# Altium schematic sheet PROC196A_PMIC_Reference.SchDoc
size 431 x 279 mm; Date: Not shown in title block; ApprovedBy: Not shown in title block; CheckedBy: Not shown in title block; Author: Not shown in title block; CompanyName: Not shown in title block; Engineer: Not shown in title block; Organization: Not shown in title block; Address1: Not shown in title block; Address2: Not shown in title block; Address3: Not shown in title block; Address4: Not shown in title block; DocumentNumber: 6; Revision: Use project parameter SCH_Rev; SheetNumber: 6; SheetTotal: 25; PageSetup: Record=PageOptions¦CenterHorizontal=True¦CenterVertical=True¦PrintScale=1.00¦XCorrection=1.00¦YCorrection=1.00¦PrintKind=0¦BorderSize=5000000¦LeftOffset=0¦BottomOffset=0¦Orientation=2¦PaperLength=1000¦PaperWidth=1000¦Scale=100¦PaperSource=15¦PrintQuality=600¦MediaType=1¦DitherType=10¦PaperKind=Letter¦PrintScaleMode=1
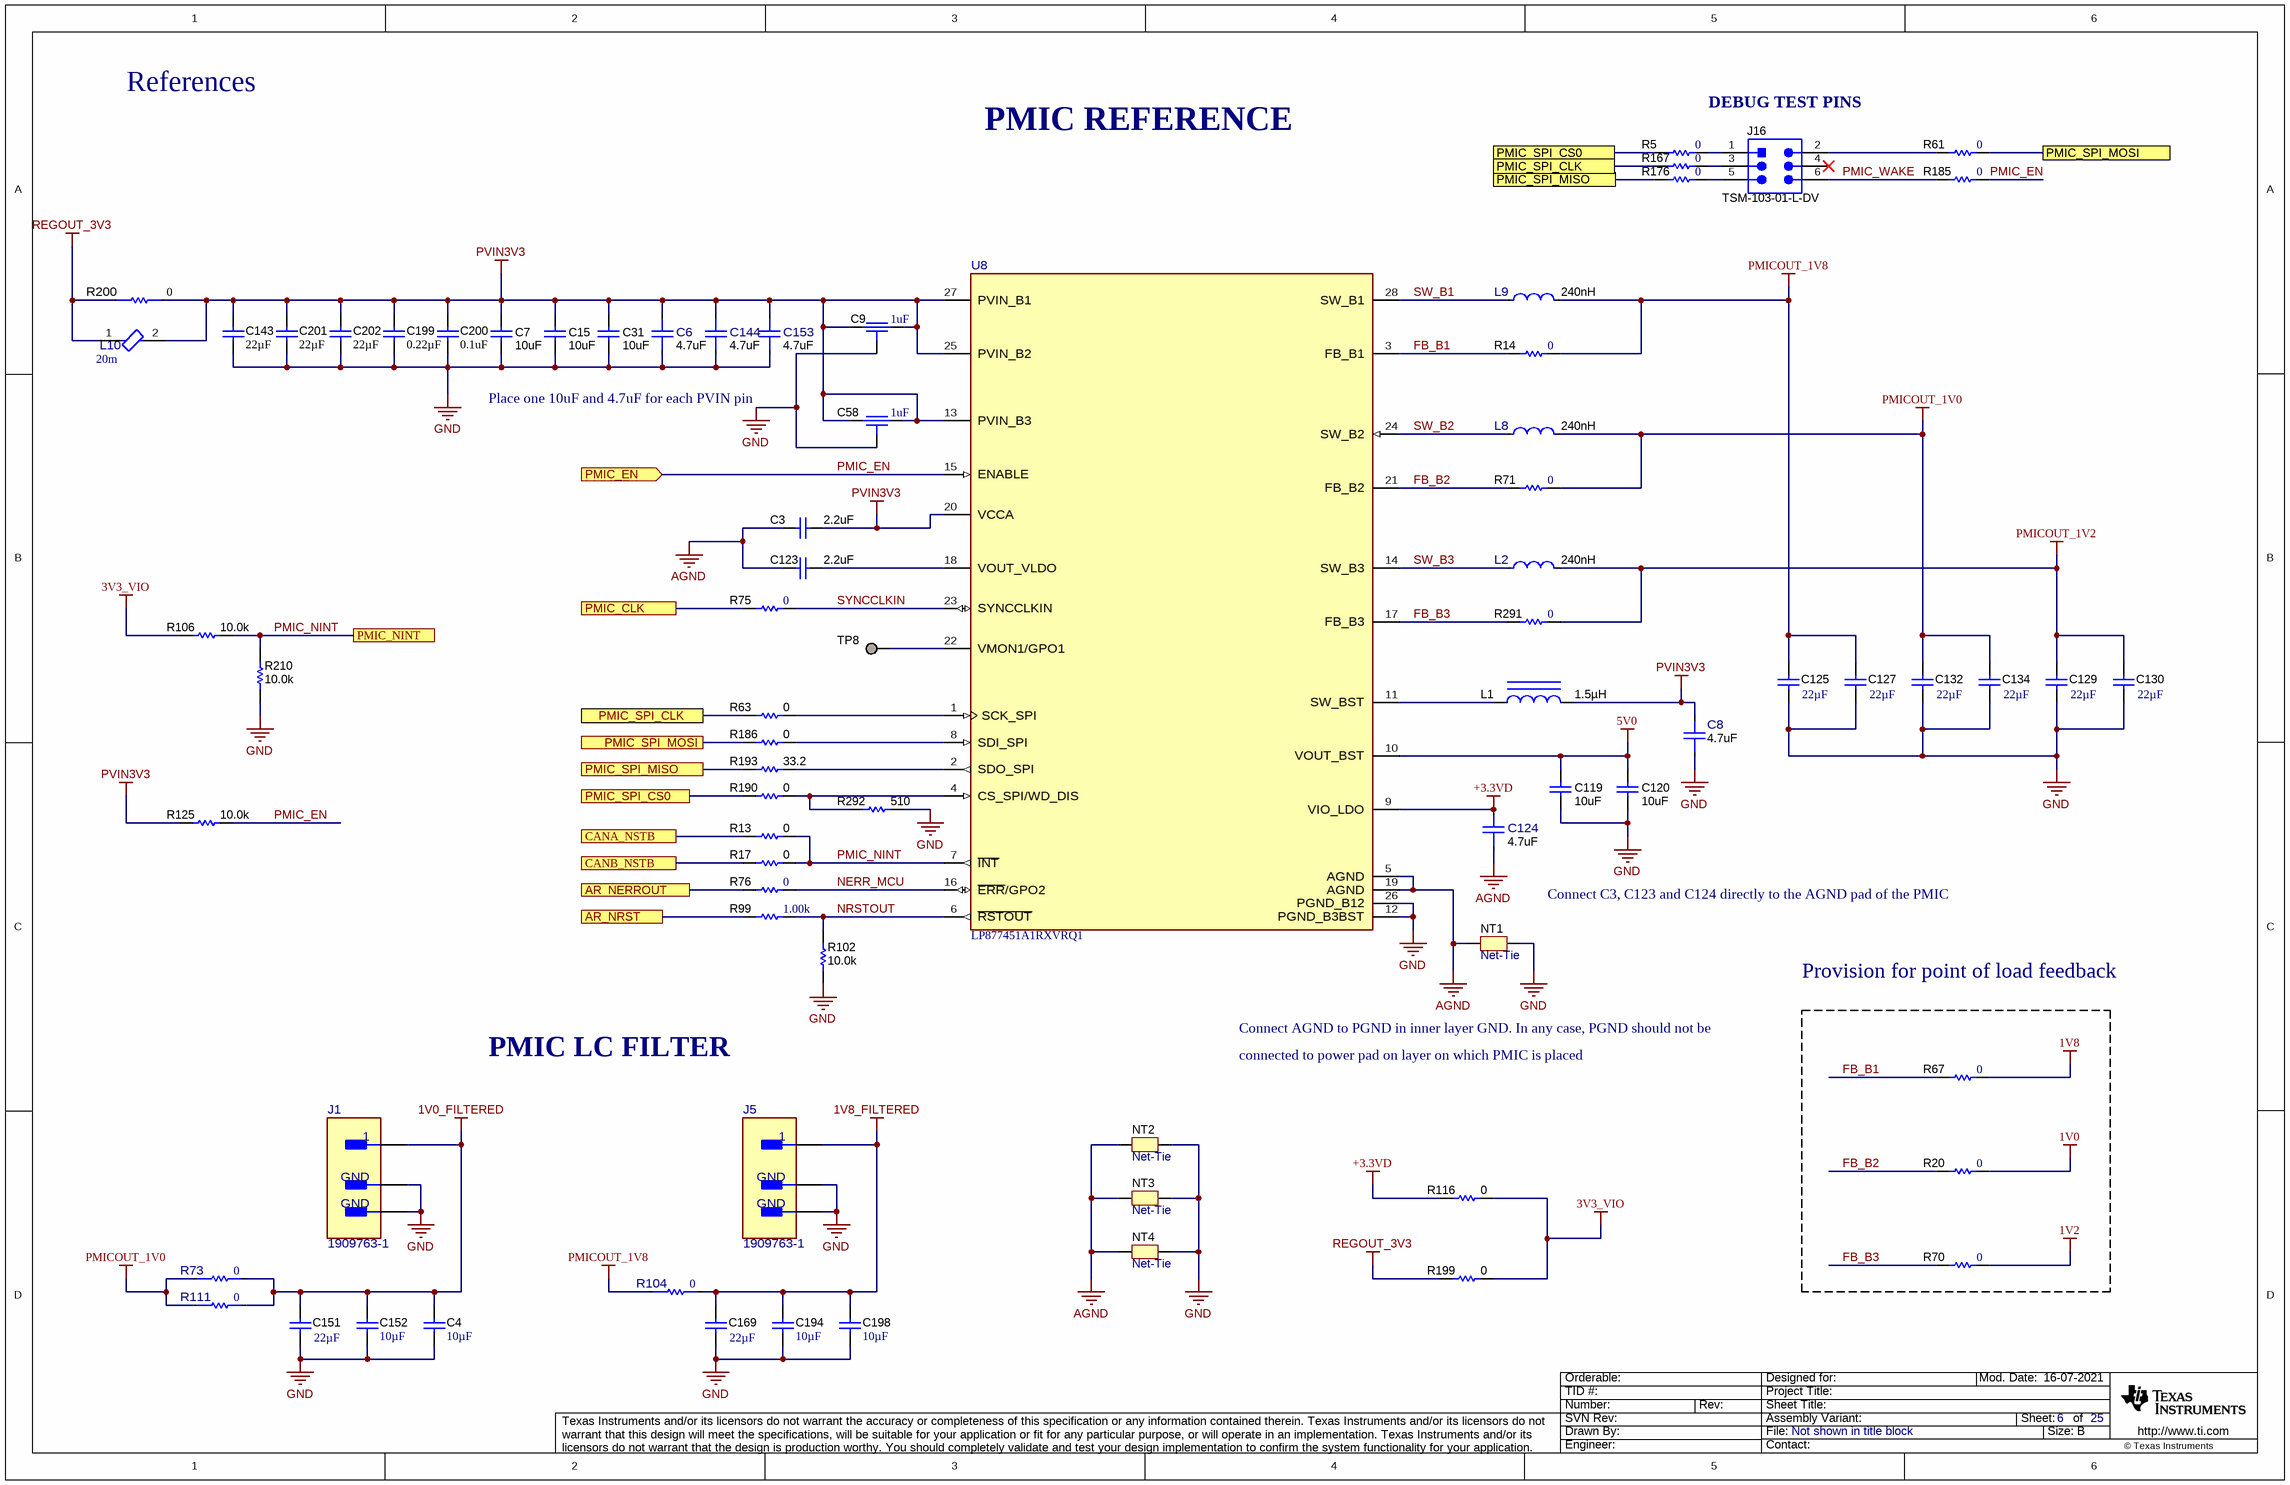
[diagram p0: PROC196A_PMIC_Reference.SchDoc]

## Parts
C3  ValueDisplayed: 2.2uF  [0603L]  (hidden comment: GCM188R70J225KE22D)
C4  Cap_F: 10µF  [0805L]  (hidden comment: C0805C106J8RACAUTO)
C6  ValueDisplayed: 4.7uF  [FP-GCJ188C70J475KE02J_0603-MFG]  (hidden comment: GCJ188C70J475KE02J)
C7  ValueDisplayed: 10uF  [0805L]  (hidden comment: GCM21BR71A106KE22L)
C8  ValueDisplayed: 4.7uF  [FP-GCJ188C70J475KE02J_0603-MFG]  (hidden comment: GCJ188C70J475KE02J)
C9  ValueDisplayed: 1uF  [FP-NFM18HC105C1C3D_0603-MFG]  (hidden comment: NFM18HC105C1C3D)
C15  ValueDisplayed: 10uF  [0805L]  (hidden comment: GCM21BR71A106KE22L)
C31  ValueDisplayed: 10uF  [0805L]  (hidden comment: GCM21BR71A106KE22L)
C58  ValueDisplayed: 1uF  [FP-NFM18HC105C1C3D_0603-MFG]  (hidden comment: NFM18HC105C1C3D)
C119  ValueDisplayed: 10uF  [0805L]  (hidden comment: GCM21BR71A106KE22L)
C120  ValueDisplayed: 10uF  [0805L]  (hidden comment: GCM21BR71A106KE22L)
C123  ValueDisplayed: 2.2uF  [0603L]  (hidden comment: GCM188R70J225KE22D)
C124  ValueDisplayed: 4.7uF  [FP-GCJ188C70J475KE02J_0603-MFG]  (hidden comment: GCJ188C70J475KE02J)
C125  ValueDisplayed: 22µF  [0805_155]  (hidden comment: CGA4J1X7T0J226M)
C127  ValueDisplayed: 22µF  [0805_155]  (hidden comment: CGA4J1X7T0J226M)
C129  ValueDisplayed: 22µF  [0805_155]  (hidden comment: CGA4J1X7T0J226M)
C130  ValueDisplayed: 22µF  [0805_155]  (hidden comment: CGA4J1X7T0J226M)
C132  ValueDisplayed: 22µF  [0805_155]  (hidden comment: CGA4J1X7T0J226M)
C134  ValueDisplayed: 22µF  [0805_155]  (hidden comment: CGA4J1X7T0J226M)
C143  ValueDisplayed: 22µF  [0805_155]  (hidden comment: CGA4J1X7T0J226M)
C144  ValueDisplayed: 4.7uF  [FP-GCJ188C70J475KE02J_0603-MFG]  (hidden comment: GCJ188C70J475KE02J)
C151  ValueDisplayed: 22µF  [0805_155]  (hidden comment: CGA4J1X7T0J226M)
C152  Cap_F: 10µF  [0805L]  (hidden comment: C0805C106J8RACAUTO)
C153  ValueDisplayed: 4.7uF  [FP-GCJ188C70J475KE02J_0603-MFG]  (hidden comment: GCJ188C70J475KE02J)
C169  ValueDisplayed: 22µF  [0805_155]  (hidden comment: CGA4J1X7T0J226M)
C194  Cap_F: 10µF  [0805L]  (hidden comment: C0805C106J8RACAUTO)
C198  Cap_F: 10µF  [0805L]  (hidden comment: C0805C106J8RACAUTO)
C199  ValueDisplayed: 0.22µF  [0402L]  (hidden comment: GCM155R71C224KE02D)
C200  ValueDisplayed: 0.1uF  [0402L]  (hidden comment: GCM155R71C104KA55D)
C201  ValueDisplayed: 22µF  [0805_155]  (hidden comment: CGA4J1X7T0J226M)
C202  ValueDisplayed: 22µF  [0805_155]  (hidden comment: CGA4J1X7T0J226M)
J1  1909763-1  [FP-1909763-1_SMT_JACK _CONN-MFG]
J5  1909763-1  [FP-1909763-1_SMT_JACK _CONN-MFG]
J16  TSM-103-01-L-DV  [Samtec_TSM-103-01-x-DV]
L1  ValueDisplayed: 1.5µH  [TFM201610ALMA]  (hidden comment: TFM201610ALMA1R5MTAA)
L2  Ind_H: 240nH  [FP-TFM201610ALMAR24MTAA_0806 (2016 Metric)-MFG]  (hidden comment: TFM201610ALMAR24MTAA)
L8  Ind_H: 240nH  [FP-TFM201610ALMAR24MTAA_0806 (2016 Metric)-MFG]  (hidden comment: TFM201610ALMAR24MTAA)
L9  Ind_H: 240nH  [FP-TFM201610ALMAR24MTAA_0806 (2016 Metric)-MFG]  (hidden comment: TFM201610ALMAR24MTAA)
L10  DCR_ohm: 20m  [FP-MPZ2012S101ATD25_0805-MFG]  (hidden comment: MPZ2012S101ATD25)
NT1  Net-Tie  [Net-Tie_50milWide_30milLong]  (net tie, no BOM)
NT2  Net-Tie  [Net-Tie_50milWide_30milLong]  (net tie, no BOM)
NT3  Net-Tie  [Net-Tie_50milWide_30milLong]  (net tie, no BOM)
NT4  Net-Tie  [Net-Tie_50milWide_30milLong]  (net tie, no BOM)
R5  ValueDisplayed: 0  [0402L]  (hidden comment: ERJ-2GE0R00X)
R13  ValueDisplayed: 0  [0402L]  (hidden comment: ERJ-2GE0R00X)
R14  ValueDisplayed: 0  [0402L]  (hidden comment: ERJ-2GE0R00X)
R17  ValueDisplayed: 0  [0402L]  (hidden comment: ERJ-2GE0R00X)
R20  ValueDisplayed: 0  [0402L]  (hidden comment: ERJ-2GE0R00X)
R61  ValueDisplayed: 0  [0402L]  (hidden comment: ERJ-2GE0R00X)
R63  ValueDisplayed: 0  [0402L]  (hidden comment: ERJ-2GE0R00X)
R67  ValueDisplayed: 0  [0402L]  (hidden comment: ERJ-2GE0R00X)
R70  ValueDisplayed: 0  [0402L]  (hidden comment: ERJ-2GE0R00X)
R71  ValueDisplayed: 0  [0402L]  (hidden comment: ERJ-2GE0R00X)
R73  value 0  [FP-HCJ0603ZT0R00_0603-MFG]  (hidden comment: HCJ0603ZT0R00)
R75  ValueDisplayed: 0  [0402L]  (hidden comment: ERJ-2GE0R00X)
R76  ValueDisplayed: 0  [0402L]  (hidden comment: ERJ-2GE0R00X)
R99  ValueDisplayed: 1.00k  [0402L]  (hidden comment: CRCW04021K00FKED)
R102  ValueDisplayed: 10.0k  [0402L]  (hidden comment: CRCW040210K0FKED)
R104  value 0  [FP-HCJ0603ZT0R00_0603-MFG]  (hidden comment: HCJ0603ZT0R00)
R106  ValueDisplayed: 10.0k  [0402L]  (hidden comment: CRCW040210K0FKED)
R111  value 0  [FP-HCJ0603ZT0R00_0603-MFG]  (hidden comment: HCJ0603ZT0R00)
R116  ValueDisplayed: 0  [0402L]  (hidden comment: CRCW04020000Z0EDHP)
R125  ValueDisplayed: 10.0k  [0402L]  (hidden comment: CRCW040210K0FKED)
R167  ValueDisplayed: 0  [0402L]  (hidden comment: ERJ-2GE0R00X)
R176  ValueDisplayed: 0  [0402L]  (hidden comment: ERJ-2GE0R00X)
R185  ValueDisplayed: 0  [0402L]  (hidden comment: ERJ-2GE0R00X)
R186  ValueDisplayed: 0  [0402L]  (hidden comment: ERJ-2GE0R00X)
R190  ValueDisplayed: 0  [0402L]  (hidden comment: ERJ-2GE0R00X)
R193  ValueDisplayed: 33.2  [0402L]  (hidden comment: CRCW040233R2FKED)
R199  ValueDisplayed: 0  [0402L]  (hidden comment: CRCW04020000Z0EDHP)
R200  Res_ohm: 0  [FP-HCJ0603ZT0R00_0603-MFG]  (hidden comment: HCJ0603ZT0R00)
R210  ValueDisplayed: 10.0k  [0402L]  (hidden comment: CRCW040210K0FKED)
R291  ValueDisplayed: 0  [0402L]  (hidden comment: ERJ-2GE0R00X)
R292  ValueDisplayed: 510  [0402L]  (hidden comment: ERJ-2GEJ511X)
TP8  TESTPOINT  [TP_25MIL-SMT]  (value not drawn)  (no BOM)
U8  LP877451A1RXVRQ1  [RXV0028A-MFG]

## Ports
AR_NERROUT, AR_NRST, CANA_NSTB, CANB_NSTB, PMIC_CLK, PMIC_EN (in), PMIC_NINT, PMIC_SPI_CLK, PMIC_SPI_CS0, PMIC_SPI_MISO, PMIC_SPI_MOSI

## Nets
1V0: R20.2
1V0_FILTERED: C4.1 C151.1 C152.1 J1.1 R73.2 R111.2
1V2: R70.2
1V8: R67.2
1V8_FILTERED: C169.1 C194.1 C198.1 J5.1 R104.2
3V3_VIO: R106.2 R116.2 R199.2
5V0: C119.1 C120.1 U8.10(VOUT_BST)
+3.3VD: C124.2 R116.1 U8.9(VIO_LDO)
AGND: C3.1 C123.1 C124.1 NT1.2 NT2.1 NT3.1 NT4.1 U8.5(AGND) U8.19(AGND)
GND: C4.2 C6.1 C7.2 C8.1 C9.2 C15.2 C31.2 C58.2 C119.2 C120.2 C125.2 C127.2 C129.2 C130.2 C132.2 C134.2 C143.2 C144.1 C151.2 C152.2 C153.1 C169.2 C194.2 C198.2 C199.2 C200.2 C201.2 C202.2 J1.2(GND) J1.3(GND) J5.2(GND) J5.3(GND) NT1.1 NT2.2 NT3.2 NT4.2 R102.2 R210.2 R292.1 U8.12(PGND_B3BST) U8.26(PGND_B12)
PMICOUT_1V0: C132.1 C134.1 L8.2 R71.2 R73.1 R111.1
PMICOUT_1V2: C129.1 C130.1 L2.2 R291.2
PMICOUT_1V8: C125.1 C127.1 L9.2 R14.2 R104.1
PVIN3V3: C3.2 C6.2 C7.1 C8.2 C9.1 C9.3 C15.1 C31.1 C58.1 C58.3 C143.1 C144.2 C153.2 C199.1 C200.1 C201.1 C202.1 L1.2 L10.2 R125.2 R200.2 U8.13(PVIN_B3) U8.20(VCCA) U8.25(PVIN_B2) U8.27(PVIN_B1)
REGOUT_3V3: L10.1 R199.1 R200.1
AR_NERROUT: R76.1 ; port AR_NERROUT
AR_NRST: R99.1 ; port AR_NRST
CANA_NSTB: R13.1 ; port CANA_NSTB
CANB_NSTB: R17.1 ; port CANB_NSTB
FB_B1: R14.1 R67.1 U8.3(FB_B1)
FB_B2: R20.1 R71.1 U8.21(FB_B2)
FB_B3: R70.1 R291.1 U8.17(FB_B3)
NERR_MCU: R76.2 U8.16(~{ERR}/GPO2)
NRSTOUT: R99.2 R102.1 U8.6(~{RSTOUT})
PMIC_CLK: R75.1 ; port PMIC_CLK
PMIC_EN: R125.1 R185.2 U8.15(ENABLE) ; port PMIC_EN
PMIC_NINT: R13.2 R17.2 R106.1 R210.1 U8.7(~{INT}) ; port PMIC_NINT
PMIC_SPI_CLK: R63.2 R167.1 ; port PMIC_SPI_CLK
PMIC_SPI_CS0: R5.1 R190.1 ; port PMIC_SPI_CS0
PMIC_SPI_MISO: R176.1 R193.2 ; port PMIC_SPI_MISO
PMIC_SPI_MOSI: R61.2 R186.2 ; port PMIC_SPI_MOSI
PMIC_WAKE: J16.6 R185.1
SW_B1: L9.1 U8.28(SW_B1)
SW_B2: L8.1 U8.24(SW_B2)
SW_B3: L2.1 U8.14(SW_B3)
SYNCCLKIN: R75.2 U8.23(SYNCCLKIN)
NetC123_2: C123.2 U8.18(VOUT_VLDO)
NetJ16_1: J16.1 R5.2
NetJ16_2: J16.2 R61.1
NetJ16_3: J16.3 R167.2
NetJ16_5: J16.5 R176.2
NetL1_1: L1.1 U8.11(SW_BST)
NetR63_1: R63.1 U8.1(SCK_SPI)
NetR186_1: R186.1 U8.8(SDI_SPI)
NetR190_2: R190.2 R292.2 U8.4(CS_SPI/WD_DIS)
NetR193_1: R193.1 U8.2(SDO_SPI)
NetTP8_1: TP8.1 U8.22(VMON1/GPO1)

Not connected (* = marked no-connect by the designer): J16 4*

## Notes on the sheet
- References
- PMIC REFERENCE
- DEBUG TEST PINS
- Place one 10uF and 4.7uF for each PVIN pin
- Connect C3, C123 and C124 directly to the AGND pad of the PMIC
- Connect AGND to PGND in inner layer GND. In any case, PGND should not be
- Provision for point of load feedback
- PMIC LC FILTER
- connected to power pad on layer on which PMIC is placed

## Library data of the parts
C3 C123 = CMP-0007134-5: CAP, CERM, 2.2 uF, 6.3 V, +/- 10%, X7R, AEC-Q200 Grade 1, 0603; Manufacturer: MuRata; TaMin_C: -55°C; Polarized: N; SizeAreaWB_mm2: 4.68; Value1: Unknown; U/M: EA; Value: 2.2uF; TaMax_C: 125°C; SizeZ_mm: 1; SizeX_mm: 1.6; SizeY_mm: 0.8; Cap_Case: 0603; Value2: 6.3V; SizeArea_mm2: 1.28; AEC Qualified: Y; Cap_F: 2.2µF; AEC Category: Q200
C4 C152 C194 C198 = CMP-0081061-1: CAP, CERM, 10 µF, 10 V,+/- 5%, X7R, AEC-Q200 Grade 1, 0805; Manufacturer: Kemet; TaMin_C: -55°C; Polarized: N; SizeAreaWB_mm2: 6.75; U/M: EA; Value: 10uF; TaMax_C: 125°C; SizeZ_mm: 1.45; SizeX_mm: 2; SizeY_mm: 1.25; Cap_Case: 0805; Value2: 10V; SizeArea_mm2: 2.5; AEC Qualified: Y; AEC Grade: 1; AEC Category: Q200
C6 C8 C124 C144 C153 = CMP-0091520-1: Cap Ceramic Multilayer 4.7uF 6.3V DC 10% SMD Paper T/R; Manufacturer: Murata; AEC Grade: Grade 1; TempCo: 22%; SizeZ_mm: 1mm; Temperature Characteristic: X7S; Cap_F: 4.7µF; Value: 4.7µF; AEC Qualified: Yes
C7 C15 C31 C119 C120 = CMP-0008017-2: CAP, CERM, 10 uF, 10 V, +/- 10%, X7R, 0805; Manufacturer: MuRata; TaMin_C: -55°C; Polarized: N; SizeAreaWB_mm2: 6.75; Value1: Unknown; U/M: EA; Value: 10uF; TaMax_C: 125°C; SizeZ_mm: 1.45; SizeX_mm: 2; SizeY_mm: 1.25; Cap_Case: 0805; Value2: 10V; SizeArea_mm2: 2.5; Cap_F: 10µF; AEC Category: Q200
C9 C58 = CMP-0088247-2: 3 Terminals Low ESL Chip Multilayer Ceramic Capacitors for Automotive; Manufacturer: Murata; VDC_V: 16V; SizeZ_mm: 0.7mm; Tolerance_%: 20%; AEC Grade: Grade 1; Cap_F: 1µF; AEC Qualified: Yes
C125 C127 C129 C130 C132 C134 = CMP-0860846-1: CAP, CERM, 22 µF, 6.3 V,+/- 20%, X7T, AEC-Q200 Grade 1, 0805; Manufacturer: TDK; Alternate PartNumber: CGA4J1X7T0J226M125AC; TaMin_C: -55°C; Polarized: N; SizeAreaWB_mm2: 6.75; U/M: EA; Value: 22uF; TaMax_C: 125°C; SizeZ_mm: 1.55; SizeX_mm: 2; SizeY_mm: 1.25; Cap_Case: 0805; Value2: 6.3V; SizeArea_mm2: 2.5; AEC Qualified: Y; AEC Grade: 1; AEC Category: Q200
C143 C201 C202 = CMP-0860846-1: CAP, CERM, 22 µF, 6.3 V,+/- 20%, X7T, AEC-Q200 Grade 1, 0805; Manufacturer: TDK; AEC Grade: 1; Value2: 6.3V; U/M: EA; Value: 22uF; TaMin_C: -55°C; TaMax_C: 125°C; SizeArea_mm2: 2.5; SizeAreaWB_mm2: 6.75; SizeX_mm: 2; Polarized: N; Cap_Case: 0805; AEC Qualified: Y; AEC Category: Q200; SizeZ_mm: 1.55; SizeY_mm: 1.25
C151 C169 = CMP-0860846-1: CAP, CERM, 22 µF, 6.3 V,+/- 20%, X7T, AEC-Q200 Grade 1, 0805; Manufacturer: TDK; TaMin_C: -55°C; Polarized: N; SizeAreaWB_mm2: 6.75; U/M: EA; Value: 22uF; TaMax_C: 125°C; SizeZ_mm: 1.55; SizeX_mm: 2; SizeY_mm: 1.25; Cap_Case: 0805; Value2: 6.3V; SizeArea_mm2: 2.5; AEC Qualified: Y; AEC Grade: 1; AEC Category: Q200
C199 = CMP-0078265-1: CAP, CERM, 0.22 µF, 16 V,+/- 10%, X7R, AEC-Q200 Grade 1, 0402; Manufacturer: MuRata; TaMin_C: -55°C; Polarized: N; SizeAreaWB_mm2: 3; U/M: EA; Value: 0.22uF; TaMax_C: 125°C; SizeZ_mm: 0.6; SizeX_mm: 1; SizeY_mm: 0.5; Cap_Case: 0402; Value2: 16V; AEC Qualified: Y; Cap_F: 220nF; AEC Category: Q200
C200 = CMP-0006351-2: CAP, CERM, 0.1 uF, 16 V, +/- 10%, X7R, 0402; Manufacturer: MuRata; TaMin_C: -55°C; Polarized: N; SizeAreaWB_mm2: 3; Value1: Unknown; U/M: EA; Value: 0.1uF; TaMax_C: 125°C; SizeZ_mm: 0.6; SizeX_mm: 1; SizeY_mm: 0.5; Cap_Case: 0402; Value2: 16V; Cap_F: 100nF; AEC Category: Q200
J1 J5 = CMP-0091846-1: U.FL (UMCC) Connector Jack, Male Pin 50Ohm Surface Mount Solder; Manufacturer: TE Connectivity; Conn Orientation: Vertical; AEC Qualified: No; SizeZ_mm: 1.5mm; Impedance: 50Ω; Frequency_Fixed: 0-6GHz; ContactFinish: Gold,Nickel; Dielectric Material: Liquid Crystal Polymer
J16 = CMP-0075648-2: Header, 2.54mm, 3x2, Gold, SMT; Manufacturer: Samtec; Pitch_mm: 2.54; Gender: Male; Cert_CSA: Y; Green_REACh: Passed; Current_A: 4.9A; Voltage_V: 475V; Shrouded: N; Green_Lifecycle: Active; Row_Count: 2
L1 = CMP-0081093-1: Inductor, Shielded, Metal Composite, 1.5 µH, 2.3 A, 0.11 ohm, AEC-Q200 Grade 0, SMD; Manufacturer: TDK; Isat: 2.8A @ 30% inductance drop; Irms: 2.3A @ 40C rise; SizeAreaWB_mm2: 7.8; DCR_ohm: 0.11; Value: 1.5uH; Imax_A: 2.3A; SizeZ_mm: 1; SizeX_mm: 2; SizeY_mm: 1.6; SizeArea_mm2: 3.2; AEC Qualified: Y; AEC Grade: 0; AEC Category: Q200
L2 L8 L9 = CMP-0091696-1: 240nH Shielded Thin Film Inductor 5A 23mOhm Max 0806 (2016 Metric); Manufacturer: TDK; SizeZ_mm: 1mm; Material: Metal; Irms: 6.5A; Shrouded: true; Value: 0.24uH; AEC Qualified: Yes; DCR_ohm: 0.023; AEC Grade: Grade 0; Test Frequency: 1MHz; Tolerance_%: 20%
L10 = CMP-0089947-1: 100 Ohms @ 100MHz 1 Power Line Ferrite Bead 0805 (2012 Metric) 4A 20mOhm; Manufacturer: TDK; AEC Grade: Grade 1; Impedance At Frequency: 100Ω @ 100MHz; SizeZ_mm: 1.05mm; AEC Qualified: Yes; Tolerance_%: 25%
NT1 = CMP-0078142-4: Single point connection between nets.
NT2-NT4 = CMP-0078142-3: Single point connection between nets.
R5 R14 R20 R61 R67 R70 R71 R75 R76 R167 R176 R185 R291 = CMP-0026992-3: RES, 0, 5%, 0.1 W, AEC-Q200 Grade 0, 0402; Manufacturer: Panasonic; Power_W: 100mW; TempCo: 600 ppm/C; Value_Code: 0000; Value: 0; EIA_Code: E24; SizeX_mm: 1; SizeY_mm: 0.5; SizeZ_mm: 0.6; Value2: 0.1W; CompType: Resistor; AEC Qualified: Y; VDC_V: 50V; AEC Category: Q200; SizeAreaWB_mm2: 3; INSTALLATION: DNP
R13 R17 R63 R186 R190 = CMP-0026992-3: RES, 0, 5%, 0.1 W, AEC-Q200 Grade 0, 0402; Manufacturer: Panasonic; Power_W: 100mW; TempCo: 600 ppm/C; Value_Code: 0000; Value: 0; EIA_Code: E24; SizeX_mm: 1; SizeY_mm: 0.5; SizeZ_mm: 0.6; Value2: 0.1W; AEC Qualified: Y; VDC_V: 50V; AEC Category: Q200; SizeAreaWB_mm2: 3
R73 R104 R111 = CMP-0091690-1: RES 0 OHM JUMPER 1/4W 0603; Manufacturer: Stackpole Electronics; Power_W: 250mW; AEC Grade: Grade 0; AEC Qualified: Yes; SizeZ_mm: 0.7mm
R99 = CMP-0026071-3: RES, 1.00 k, 1%, 0.063 W, AEC-Q200 Grade 0, 0402; Manufacturer: Vishay-Dale; Power_W: 63mW; TempCo: 100 ppm/C; Value_Code: 1k00; Value: 1.00k; EIA_Code: E96; Res_ohm: 1k; SizeX_mm: 1; SizeY_mm: 0.5; SizeZ_mm: 0.6; Value2: 0.063W; AEC Qualified: Y; VDC_V: 50V; AEC Category: Q200; AEC Grade: 0
R102 R106 R125 R210 = CMP-0025958-3: RES, 10.0 k, 1%, 0.063 W, AEC-Q200 Grade 0, 0402; Manufacturer: Vishay-Dale; Power_W: 63mW; TempCo: 100 ppm/C; Value_Code: 10k0; Value: 10.0k; EIA_Code: E96; Res_ohm: 10k; SizeX_mm: 1; SizeY_mm: 0.5; SizeZ_mm: 0.6; Value2: 0.063W; AEC Qualified: Y; VDC_V: 50V; AEC Category: Q200; AEC Grade: 0
R116 R199 = CMP-0081856-1: RES, 0, 0%, 0.2 W, AEC-Q200 Grade 0, 0402; Manufacturer: Vishay-Dale; SizeAreaWB_mm2: 3; SizeArea_mm2: 0.5; AEC Qualified: Y; AEC Category: Q200; Value: 0; SizeZ_mm: 0.6; Power_W: 200mW; VDC_V: 50V; Value2: 0.2W; SizeX_mm: 1
R193 = CMP-0026299-2: RES, 33.2, 1%, 0.063 W, AEC-Q200 Grade 0, 0402; Manufacturer: Vishay-Dale; Power_W: 63mW; TempCo: 100 ppm/C; Value_Code: 33R2; Value: 33.2; EIA_Code: E96; SizeX_mm: 1; SizeY_mm: 0.5; SizeZ_mm: 0.6; Value2: 0.063W; AEC Qualified: Y; VDC_V: 50V; AEC Category: Q200; AEC Grade: 0
R200 = CMP-0091690-1: RES 0 OHM JUMPER 1/4W 0603; Manufacturer: Stackpole Electronics; Power_W: 250mW; AEC Grade: Grade 0; AEC Qualified: Yes; SizeZ_mm: 0.7mm; Value: 0
R292 = CMP-0078212-1: RES, 510, 5%, 0.1 W, AEC-Q200 Grade 0, 0402; Manufacturer: Panasonic; Value_Code: 510R; SizeArea_mm2: 0.5; AEC Qualified: Y; AEC Category: Q200; Value: 510; SizeZ_mm: 0.6; EIA_Code: E24; TempCo: 200 ppm/C; AEC Grade: 0; Power_W: 100mW; VDC_V: 50V; Value2: 0.1W; U/M: EA; SizeX_mm: 1
TP8 = CMP-0078143-3: TEST POINT.  No entry in BOM.
U8 = CMP-0091078-3: Three Buck Converters and 5-V Boost for AWR and IWR Radar Sensors; Manufacturer: Texas Instruments; CompType: IC; AEC Category: Q200; Standoff Height: 0mm; Min Supply Voltage: 3V; TJmax_C: +150°C; Switching Frequency: 4.4-8.8-17.6MHz; Nominal Supply Current: 3uA; TaMax_C: +125°C; Max Supply Voltage: 4V; TaMin_C: -40°C; Number Of Outputs: 4; SizeZ_mm: 1mm; Output Voltage: 0.9-1.9V; AEC Qualified: Yes; AEC Grade: Grade 1; Output Type: AdjustableProgrammable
